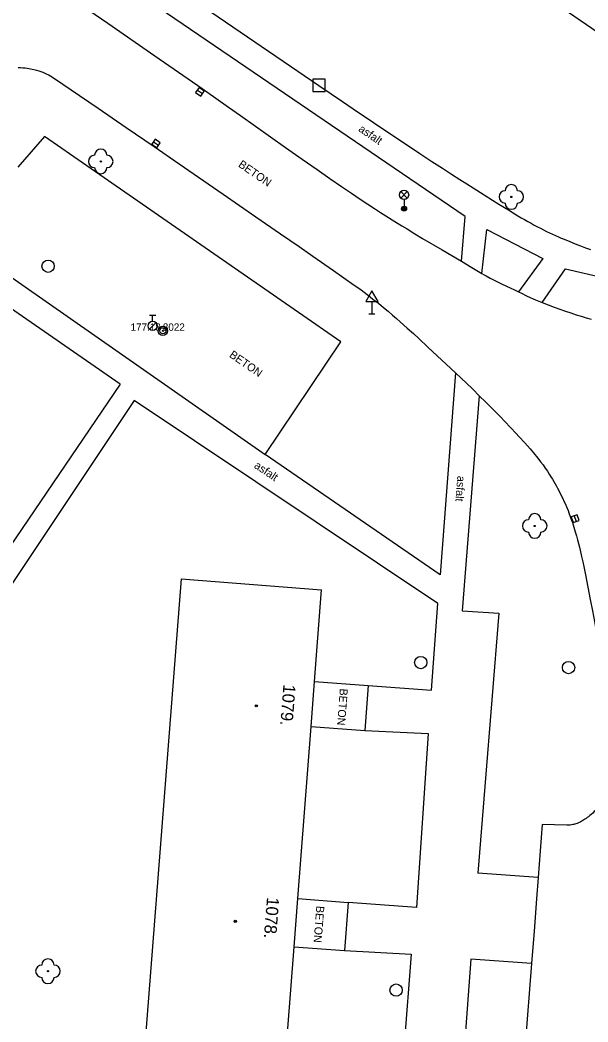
# Model space of a CAD drawing. Extents: x -539515 to -538098, y -1182060 to -1180157.
# Drawn here: x -538797.8 to -538751.7, y -1181508.2 to -1181426.9 of the extents above; entities that cross this region are included whole.
import ezdxf

# ---------------------------------------------------------------- set-up
doc = ezdxf.new("R2010")
doc.units = 0
for name, color, linetype in [('Vrstva 10', 7, 'Continuous'), ('Vrstva 11', 7, 'Continuous'), ('Vrstva 21', 7, 'Continuous'), ('Vrstva 22', 7, 'Continuous'), ('Vrstva 23', 7, 'Continuous'), ('Vrstva 26', 7, 'Continuous'), ('Vrstva 27', 7, 'Continuous'), ('Vrstva 28', 7, 'Continuous'), ('Vrstva 33', 7, 'Continuous'), ('Vrstva 34', 7, 'Continuous'), ('Vrstva 39', 7, 'Continuous'), ('Vrstva 40', 7, 'Continuous'), ('Vrstva 47', 7, 'Continuous'), ('Vrstva 5', 7, 'Continuous')]:
    doc.layers.add(name, color=color, linetype=linetype)

msp = doc.modelspace()

# ---------------------------------------------------------------- linework, layer by layer
at = {"layer": 'Vrstva 10'}
for p, q in [((-538771.77, -1181452.98), (-538795.82, -1181436.32)), ((-538808.9, -1181440.49), (-538777.91, -1181462.11)), ((-538777.91, -1181462.11), (-538771.77, -1181452.98)), ((-538756.064, -1181500.819), (-538756.27, -1181503.44)), ((-538756.27, -1181503.44), (-538756.99, -1181512.52))]:
    msp.add_line(p, q, dxfattribs=at)
for points in [[(-538794.62, -1181424.41), (-538793.935, -1181424.88), (-538793.25, -1181425.35), (-538790.692, -1181427.114), (-538786.861, -1181429.767)], [(-538786.861, -1181429.767), (-538783.03, -1181432.42), (-538781.919, -1181433.192), (-538780.88, -1181433.921), (-538779.908, -1181434.607), (-538776.268, -1181437.19), (-538774.901, -1181438.155)], [(-538797.971, -1181430.701), (-538797.772, -1181430.712), (-538797.586, -1181430.727), (-538797.412, -1181430.746), (-538797.25, -1181430.767), (-538797.099, -1181430.791), (-538796.958, -1181430.816), (-538796.827, -1181430.843), (-538796.705, -1181430.87), (-538796.591, -1181430.898), (-538796.485, -1181430.926), (-538796.289, -1181430.985), (-538796.12, -1181431.041), (-538795.974, -1181431.095), (-538795.848, -1181431.145), (-538795.739, -1181431.192), (-538795.645, -1181431.235), (-538795.483, -1181431.315), (-538795.364, -1181431.379), (-538795.276, -1181431.429), (-538795.147, -1181431.507), (-538795.02, -1181431.59)], [(-538795.02, -1181431.59), (-538792.994, -1181432.97), (-538791.476, -1181434.007), (-538789.202, -1181435.566), (-538786.93, -1181437.13), (-538784.895, -1181438.532)], [(-538795.82, -1181436.32), (-538796.915, -1181437.555), (-538798.01, -1181438.79)], [(-538784.895, -1181438.532), (-538781.331, -1181440.98), (-538778.66, -1181442.817), (-538776.658, -1181444.197), (-538775.158, -1181445.235), (-538774.034, -1181446.016)], [(-538774.901, -1181438.155), (-538773.701, -1181438.994), (-538772.648, -1181439.723), (-538771.723, -1181440.356), (-538770.911, -1181440.905), (-538770.198, -1181441.381), (-538769.572, -1181441.794), (-538769.022, -1181442.153), (-538768.54, -1181442.465), (-538768.117, -1181442.736), (-538767.373, -1181443.207), (-538766.813, -1181443.555), (-538766.392, -1181443.815), (-538765.757, -1181444.2)], [(-538765.757, -1181444.2), (-538765.12, -1181444.58), (-538763.545, -1181445.51), (-538761.97, -1181446.44), (-538761.14, -1181446.93), (-538760.31, -1181447.42), (-538760.13, -1181447.524), (-538759.96, -1181447.62), (-538759.639, -1181447.794), (-538759.356, -1181447.941), (-538759.106, -1181448.067), (-538758.666, -1181448.283), (-538758.003, -1181448.6), (-538757.671, -1181448.759), (-538757.34, -1181448.92), (-538757.103, -1181449.035), (-538756.689, -1181449.23), (-538756.377, -1181449.372)], [(-538774.034, -1181446.016), (-538772.35, -1181447.19), (-538770.67, -1181448.37), (-538770.393, -1181448.567), (-538770.127, -1181448.761), (-538769.87, -1181448.951), (-538769.624, -1181449.137), (-538769.386, -1181449.319), (-538769.157, -1181449.498), (-538768.718, -1181449.847), (-538768.31, -1181450.18), (-538767.93, -1181450.497), (-538767.577, -1181450.797), (-538767.248, -1181451.08), (-538766.942, -1181451.348), (-538766.371, -1181451.856), (-538765.875, -1181452.305), (-538765.444, -1181452.701), (-538764.693, -1181453.398)], [(-538756.377, -1181449.372), (-538756.141, -1181449.476), (-538755.961, -1181449.553), (-538755.689, -1181449.667), (-538755.41, -1181449.78), (-538754.915, -1181449.974), (-538754.434, -1181450.155), (-538753.968, -1181450.324), (-538753.515, -1181450.483), (-538753.076, -1181450.631), (-538752.65, -1181450.77), (-538752.237, -1181450.9), (-538751.837, -1181451.022), (-538751.448, -1181451.136)], [(-538764.693, -1181453.398), (-538762.45, -1181455.5), (-538761.963, -1181455.958), (-538761.6, -1181456.304), (-538761.059, -1181456.826), (-538760.52, -1181457.35), (-538759.988, -1181457.872), (-538759.528, -1181458.332), (-538759.129, -1181458.738), (-538758.781, -1181459.094), (-538758.479, -1181459.408), (-538757.954, -1181459.962), (-538757.563, -1181460.381), (-538757.271, -1181460.697), (-538756.834, -1181461.176), (-538756.4, -1181461.66), (-538756.261, -1181461.818)], [(-538756.261, -1181461.818), (-538756.128, -1181461.973), (-538756.001, -1181462.125), (-538755.879, -1181462.273), (-538755.764, -1181462.418), (-538755.544, -1181462.702), (-538755.344, -1181462.972), (-538755.162, -1181463.229), (-538754.995, -1181463.472), (-538754.843, -1181463.703), (-538754.704, -1181463.922), (-538754.577, -1181464.129), (-538754.46, -1181464.325), (-538754.353, -1181464.509), (-538754.255, -1181464.684), (-538754.164, -1181464.849), (-538754, -1181465.161), (-538753.862, -1181465.437), (-538753.744, -1181465.68), (-538753.645, -1181465.895), (-538753.56, -1181466.084), (-538753.417, -1181466.418), (-538753.315, -1181466.671), (-538753.24, -1181466.861), (-538753.133, -1181467.15), (-538753.03, -1181467.44), (-538752.963, -1181467.639), (-538752.838, -1181468.026), (-538752.728, -1181468.389), (-538752.63, -1181468.73), (-538752.542, -1181469.05), (-538752.463, -1181469.351), (-538752.393, -1181469.633), (-538752.329, -1181469.898), (-538752.214, -1181470.395)], [(-538752.214, -1181470.395), (-538752.118, -1181470.831), (-538752.038, -1181471.213), (-538751.902, -1181471.883), (-538751.706, -1181472.89), (-538751.51, -1181473.9), (-538751.331, -1181474.817), (-538751.166, -1181475.68), (-538751.016, -1181476.49), (-538750.88, -1181477.251), (-538750.756, -1181477.966), (-538750.644, -1181478.636), (-538750.543, -1181479.265), (-538750.452, -1181479.855)], [(-538750.641, -1181490.564), (-538750.75, -1181490.68), (-538750.903, -1181490.836), (-538751.046, -1181490.98), (-538751.182, -1181491.11), (-538751.31, -1181491.229), (-538751.431, -1181491.336), (-538751.545, -1181491.433), (-538751.652, -1181491.52), (-538751.754, -1181491.598), (-538751.85, -1181491.668), (-538751.941, -1181491.731), (-538752.027, -1181491.787), (-538752.108, -1181491.837), (-538752.185, -1181491.881)], [(-538755.41, -1181492.15), (-538755.57, -1181494.3), (-538755.73, -1181496.45), (-538755.862, -1181498.198), (-538756.064, -1181500.819)], [(-538752.185, -1181491.881), (-538752.258, -1181491.92), (-538752.326, -1181491.955), (-538752.455, -1181492.016), (-538752.57, -1181492.062), (-538752.672, -1181492.098), (-538752.762, -1181492.126), (-538752.842, -1181492.147), (-538752.912, -1181492.164), (-538753.036, -1181492.186), (-538753.13, -1181492.199), (-538753.202, -1181492.205), (-538753.31, -1181492.21), (-538753.42, -1181492.21), (-538754.415, -1181492.18), (-538755.41, -1181492.15)]]:
    msp.add_lwpolyline(points, dxfattribs=at)
at = {"layer": 'Vrstva 11'}
for p, q in [((-538795.05, -1181417.505), (-538773.55, -1181432.16)), ((-538761.68, -1181442.8), (-538790.14, -1181423.41)), ((-538789.68, -1181456.41), (-538810.13, -1181442.28)), ((-538761.97, -1181446.44), (-538761.68, -1181442.8)), ((-538760.31, -1181447.42), (-538759.9, -1181443.86)), ((-538759.9, -1181443.86), (-538755.37, -1181446.21)), ((-538755.37, -1181446.21), (-538757.34, -1181448.92)), ((-538755.41, -1181449.78), (-538753.51, -1181447.04)), ((-538762.45, -1181455.5), (-538763.7, -1181471.88)), ((-538789.68, -1181456.41), (-538801.91, -1181474.39)), ((-538760.52, -1181457.35), (-538761.9, -1181474.82)), ((-538788.56, -1181457.73), (-538811.19, -1181491.67)), ((-538763.89, -1181474.22), (-538788.56, -1181457.73)), ((-538763.7, -1181471.88), (-538777.91, -1181462.11)), ((-538764.39, -1181481.26), (-538763.89, -1181474.22)), ((-538761.9, -1181474.82), (-538758.94, -1181474.99)), ((-538758.94, -1181474.99), (-538760.645, -1181496.102)), ((-538773.903, -1181480.534), (-538769.55, -1181480.87)), ((-538769.55, -1181480.87), (-538769.82, -1181484.53)), ((-538769.55, -1181480.87), (-538764.39, -1181481.26)), ((-538774.185, -1181484.194), (-538769.82, -1181484.53)), ((-538769.82, -1181484.53), (-538764.68, -1181484.78)), ((-538764.68, -1181484.78), (-538765.62, -1181498.9)), ((-538755.73, -1181496.45), (-538760.645, -1181496.102)), ((-538775.261, -1181498.157), (-538771.168, -1181498.472)), ((-538771.168, -1181498.472), (-538771.47, -1181502.39)), ((-538765.62, -1181498.9), (-538771.168, -1181498.472)), ((-538775.563, -1181502.075), (-538771.47, -1181502.39)), ((-538771.47, -1181502.39), (-538766.05, -1181502.69)), ((-538766.05, -1181502.69), (-538767.17, -1181517.14)), ((-538761.21, -1181503.09), (-538763.049, -1181528.196)), ((-538756.27, -1181503.44), (-538761.21, -1181503.09))]:
    msp.add_line(p, q, dxfattribs=at)
for points in [[(-538773.55, -1181432.16), (-538772.554, -1181432.839), (-538771.623, -1181433.472), (-538770.752, -1181434.064), (-538769.121, -1181435.168), (-538767.692, -1181436.128), (-538766.438, -1181436.964), (-538765.337, -1181437.693)], [(-538765.337, -1181437.693), (-538764.368, -1181438.329), (-538763.516, -1181438.884), (-538762.767, -1181439.369), (-538762.108, -1181439.792), (-538761.528, -1181440.162), (-538761.019, -1181440.485), (-538760.122, -1181441.05), (-538759.444, -1181441.473), (-538758.933, -1181441.79), (-538758.161, -1181442.266), (-538757.382, -1181442.74), (-538757.112, -1181442.902), (-538756.844, -1181443.058), (-538756.579, -1181443.209), (-538756.318, -1181443.354), (-538756.059, -1181443.494)], [(-538756.059, -1181443.494), (-538755.803, -1181443.629), (-538755.55, -1181443.76), (-538755.299, -1181443.886), (-538755.052, -1181444.007), (-538754.808, -1181444.125), (-538754.567, -1181444.238), (-538754.328, -1181444.347), (-538754.093, -1181444.453), (-538753.86, -1181444.555), (-538753.631, -1181444.653), (-538753.177, -1181444.841), (-538752.735, -1181445.017), (-538752.305, -1181445.18), (-538751.886, -1181445.333), (-538751.479, -1181445.475)], [(-538753.51, -1181447.04), (-538750.48, -1181447.76), (-538747.45, -1181448.48), (-538746.899, -1181448.607), (-538746.381, -1181448.72), (-538745.893, -1181448.821), (-538745.435, -1181448.91), (-538745.004, -1181448.99), (-538744.599, -1181449.061), (-538744.219, -1181449.125), (-538743.862, -1181449.182)]]:
    msp.add_lwpolyline(points, dxfattribs=at)
at = {"layer": 'Vrstva 21'}
for radius in [0.375, 0.05]:
    msp.add_circle((-538786.22, -1181452.08), radius, dxfattribs=at)
at = {"layer": 'Vrstva 22'}
for centre in [(-538791.26, -1181438.33), (-538757.92, -1181441.21), (-538756.02, -1181467.92), (-538795.55, -1181504.06)]:
    msp.add_circle(centre, 0.05, dxfattribs=at)
for centre, start, end in [((-538791.76, -1181438.33), 90, 270), ((-538791.26, -1181437.83), 0, 180), ((-538790.76, -1181438.33), 270, 90), ((-538791.26, -1181438.83), 180, 0), ((-538757.92, -1181440.71), 0, 180), ((-538758.42, -1181441.21), 90, 270), ((-538757.42, -1181441.21), 270, 90), ((-538757.92, -1181441.71), 180, 0), ((-538756.02, -1181467.42), 0, 180), ((-538756.52, -1181467.92), 90, 270), ((-538755.52, -1181467.92), 270, 90), ((-538756.02, -1181468.42), 180, 0), ((-538795.55, -1181503.56), 0, 180), ((-538796.05, -1181504.06), 90, 270), ((-538795.05, -1181504.06), 270, 90), ((-538795.55, -1181504.56), 180, 0)]:
    msp.add_arc(centre, 0.5, start, end, dxfattribs=at)
at = {"layer": 'Vrstva 26'}
msp.add_lwpolyline([(-538774.05, -1181432.66), (-538773.05, -1181432.66), (-538773.05, -1181431.66), (-538774.05, -1181431.66)], close=True, dxfattribs=at)
at = {"layer": 'Vrstva 27'}
for p, q in [((-538783.414, -1181432.538), (-538783.002, -1181432.822)), ((-538786.979, -1181436.733), (-538786.567, -1181437.017)), ((-538752.817, -1181467.097), (-538752.657, -1181467.571))]:
    msp.add_line(p, q, dxfattribs=at)
for points in [[(-538783.556, -1181432.743), (-538783.145, -1181433.028), (-538782.86, -1181432.617), (-538783.271, -1181432.332)], [(-538787.121, -1181436.939), (-538786.709, -1181437.223), (-538786.425, -1181436.811), (-538786.837, -1181436.527)], [(-538753.054, -1181467.178), (-538752.893, -1181467.651), (-538752.42, -1181467.49), (-538752.581, -1181467.017)]]:
    msp.add_lwpolyline(points, close=True, dxfattribs=at)
for centre in [(-538795.54, -1181446.84), (-538765.28, -1181479.01), (-538753.27, -1181479.42), (-538767.28, -1181505.6)]:
    msp.add_circle(centre, 0.5, dxfattribs=at)
at = {"layer": 'Vrstva 28'}
for p, q in [((-538787.3, -1181450.805), (-538786.8, -1181450.805)), ((-538787.05, -1181451.305), (-538787.05, -1181450.805)), ((-538787.308, -1181451.952), (-538786.778, -1181451.422))]:
    msp.add_line(p, q, dxfattribs=at)
for centre, radius in [((-538787.05, -1181451.68), 0.375), ((-538786.22, -1181452.08), 0.25)]:
    msp.add_circle(centre, radius, dxfattribs=at)
at = {"layer": 'Vrstva 33'}
for p, q in [((-538766.895, -1181441.31), (-538766.365, -1181440.78)), ((-538766.895, -1181440.78), (-538766.365, -1181441.31)), ((-538766.63, -1181441.42), (-538766.63, -1181442.17))]:
    msp.add_line(p, q, dxfattribs=at)
for centre, radius in [((-538766.63, -1181441.045), 0.375), ((-538766.63, -1181442.17), 0.2), ((-538766.63, -1181442.17), 0.145), ((-538766.63, -1181442.17), 0.0876)]:
    msp.add_circle(centre, radius, dxfattribs=at)
at = {"layer": 'Vrstva 34'}
for p, q in [((-538769.243, -1181449.691), (-538769.243, -1181450.709)), ((-538769.493, -1181450.709), (-538768.993, -1181450.709))]:
    msp.add_line(p, q, dxfattribs=at)
msp.add_lwpolyline([(-538769.743, -1181449.691), (-538768.743, -1181449.691), (-538769.243, -1181448.825)], close=True, dxfattribs=at)
at = {"layer": 'Vrstva 39'}
for centre, radius in [((-538778.629, -1181482.521), 0.09), ((-538778.629, -1181482.521), 0.0398), ((-538780.334, -1181500.007), 0.09), ((-538780.334, -1181500.007), 0.0398)]:
    msp.add_circle(centre, radius, dxfattribs=at)
at = {"layer": 'Vrstva 5'}
for q in [(-538788.97, -1181526.53), (-538773.33, -1181473.1)]:
    msp.add_line((-538784.73, -1181472.22), q, dxfattribs=at)
for points in [[(-538731.98, -1181440.83), (-538761.787, -1181420.406)], [(-538777.518, -1181527.437), (-538776.947, -1181520.023), (-538776.666, -1181516.387), (-538775.563, -1181502.075), (-538775.261, -1181498.157), (-538774.185, -1181484.194), (-538773.903, -1181480.534), (-538773.33, -1181473.1)]]:
    msp.add_lwpolyline(points, dxfattribs=at)

# ---------------------------------------------------------------- texts
at = {"layer": 'Vrstva 22'}
msp.add_text('177.18 ', height=0.6, dxfattribs=at).set_placement((-538788.844, -1181452.08))
at = {"layer": 'Vrstva 23'}
msp.add_text('8022', height=0.6, dxfattribs=at).set_placement((-538786.22, -1181452.08))
at = {"layer": 'Vrstva 40'}
for s, rotation, p in [('asfalt', 325.73312, (-538770.388, -1181435.835)), ('BETON', 325.43619, (-538780.15, -1181438.714)), ('BETON', 325.28874, (-538780.878, -1181454.163)), ('asfalt', 326.24031, (-538778.862, -1181463.158)), ('asfalt', 265.63607, (-538762.299, -1181463.839)), ('BETON', 265.59267, (-538771.841, -1181481.097)), ('BETON', 265.59267, (-538773.749, -1181498.741))]:
    msp.add_text(s, height=0.65, rotation=rotation, dxfattribs=at).set_placement(p)
at = {"layer": 'Vrstva 47'}
for s, p in [('1079.', (-538776.427, -1181480.756)), ('1078.', (-538777.759, -1181498.031))]:
    msp.add_text(s, height=1, rotation=265.59267, dxfattribs=at).set_placement(p)

doc.saveas('drawing.dxf')
